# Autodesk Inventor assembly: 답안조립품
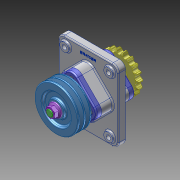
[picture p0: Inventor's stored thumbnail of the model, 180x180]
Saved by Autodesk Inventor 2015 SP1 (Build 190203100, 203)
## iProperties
Created: 2026-07
Part Number: 답안조립품
Document SubType Name: Assembly
Designer: user
Author: user
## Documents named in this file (12)
- C:\Users\user\Desktop\760705V1001\답안조립품.iam
- C:\Users\user\Desktop\760705V1001\본체.ipt
- C:\Users\user\Desktop\760705V1001\가져온 구성요소\6각 구멍붙이 볼트 M6x16\6각 구멍붙이 볼트 M6x16.ipt
- C:\Users\user\Desktop\760705V1001\가져온 구성요소\6각 플랜지 너트 M16\6각 플랜지 너트 M16.ipt
- C:\Users\user\Desktop\760705V1001\가져온 구성요소\V-벨트풀리\V-벨트풀리.ipt
- C:\Users\user\Desktop\760705V1001\가져온 구성요소\깊은 홈 볼 베어링 6206\깊은 홈 볼 베어링 6206.ipt
- C:\Users\user\Desktop\760705V1001\가져온 구성요소\오일 실 30 45 8\오일 실 30 45 8.ipt
- C:\Users\user\Desktop\760705V1001\가져온 구성요소\체인 스프로킷\체인 스프로킷.ipt
- C:\Users\user\Desktop\760705V1001\가져온 구성요소\축\축.ipt
- C:\Users\user\Desktop\760705V1001\가져온 구성요소\칼라\칼라.ipt
- C:\Users\user\Desktop\760705V1001\가져온 구성요소\커버\커버.ipt
- C:\Users\user\Desktop\760705V1001\가져온 구성요소\평행 키 6x6x20\평행 키 6x6x20.ipt
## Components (11 placed, 3 different names)
1. 6각 구멍붙이 볼트 M6x16:1
2. 6각 플랜지 너트 M16:1
3. V-벨트풀리:1
4. 6각 구멍붙이 볼트 M6x16:2
5. 6각 구멍붙이 볼트 M6x16:3
6. 6각 구멍붙이 볼트 M6x16:4
7. 6각 구멍붙이 볼트 M6x16:5
8. 6각 구멍붙이 볼트 M6x16:6
9. 6각 구멍붙이 볼트 M6x16:7
10. 6각 구멍붙이 볼트 M6x16:8
11. 6각 플랜지 너트 M16:2
